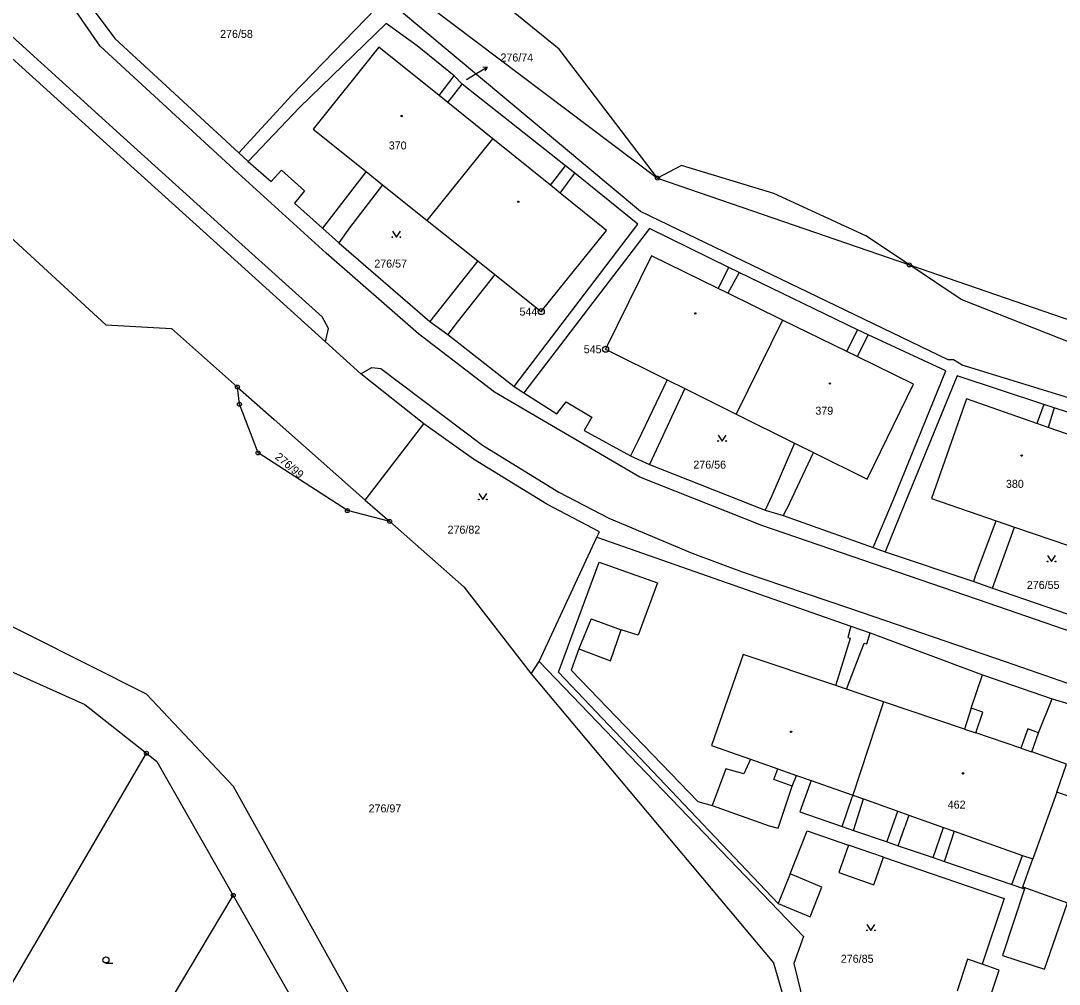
# Model space of a CAD drawing. Extents: x -745926 to -742978, y -968282 to -965689.
# Drawn here: x -744856.3 to -744726.5, y -967027 to -966906.6 of the extents above; entities that cross this region are included whole.
import ezdxf

# ---------------------------------------------------------------- set-up
doc = ezdxf.new("R2010")
doc.units = 0
for name, color, linetype in [('Hranice parcel', 7, 'Continuous'), ('Parcelní čísla', 7, 'Continuous'), ('Pop  PČ popisy', 7, 'Continuous'), ('Vnitřní kresba', 7, 'Continuous'), ('Značky bodu BP', 7, 'Continuous'), ('Značky budov', 7, 'Continuous'), ('Značky kultur', 7, 'Continuous')]:
    doc.layers.add(name, color=color, linetype=linetype)

msp = doc.modelspace()

# ---------------------------------------------------------------- linework, layer by layer
at = {"layer": 'Hranice parcel'}
for p, q in [((-744829.06, -966923.12), (-744827.88, -966924.19)), ((-744794.62, -966952.29), (-744793.43, -966953.08)), ((-744813.24, -966966.49), (-744805.93, -966956.99)), ((-744813.24, -966966.49), (-744810.19, -966969.17)), ((-744791.49, -966986.68), (-744784.3, -966971.12)), ((-744749.76, -966972.44), (-744748.26, -966972.98)), ((-744792.49, -966988.21), (-744791.49, -966986.68)), ((-744866.87, -967042.98), (-744840.6, -966998.13)), ((-744850.19, -967050.17), (-744829.75, -967015.89)), ((-744829.75, -967015.89), (-744805.47, -967058.42))]:
    msp.add_line(p, q, dxfattribs=at)
for points in [[(-744627.78, -966987.01), (-744649.71, -966979.39), (-744654.61, -966977.79), (-744692.27, -966963.9), (-744738.66, -966949.62), (-744739.71, -966948.97), (-744740.38, -966948.96), (-744778.84, -966930.46), (-744815.82, -966899.53), (-744818.58, -966883.89), (-744822.45, -966860.57), (-744822.45, -966858.85), (-744822.42, -966856.77), (-744822.4, -966854.94), (-744822.37, -966853.08), (-744822.37, -966851.59), (-744822.35, -966814.99), (-744823.48, -966815.03), (-744822.59, -966803.93), (-744824.77, -966768.68), (-744832.65, -966757.45)], [(-744812.79, -966854.17), (-744813.4, -966862.64), (-744813.73, -966867.2), (-744808, -966902.66), (-744776.73, -966926.26), (-744745.23, -966937.12), (-744720.11, -966945.77), (-744707.11, -966950.26), (-744691.81, -966955.53), (-744673.4, -966962.06), (-744650.22, -966970.28), (-744647.24, -966971.34)], [(-744805.93, -966956.99), (-744813.81, -966950.73), (-744818.23, -966946.73), (-744830.92, -966935.24), (-744845.58, -966922), (-744860.15, -966908.86), (-744870.54, -966900.46), (-744883.43, -966892.96), (-744896.32, -966886.96), (-744915.31, -966879.05), (-744921.62, -966878.86)], [(-744829.06, -966923.12), (-744822.41, -966915.9), (-744811.89, -966905.04), (-744817.34, -966900.06), (-744819.79, -966885.67), (-744822.12, -966886.29)], [(-744851.07, -966894.18), (-744849.82, -966901.7), (-744844.56, -966908.83), (-744829.06, -966923.12)], [(-744794.62, -966952.29), (-744779.16, -966932.02), (-744787.05, -966925.66), (-744788.22, -966924.73), (-744801.14, -966914.51), (-744802.14, -966913.51), (-744806.78, -966909.73), (-744810.65, -966906.94), (-744821.48, -966917.45), (-744827.88, -966924.19)], [(-744813.15, -966925.46), (-744811.1, -966927.1), (-744805.51, -966931.56), (-744799.19, -966936.61), (-744797.05, -966938.32), (-744791.25, -966942.95), (-744783.08, -966932.8), (-744788.9, -966928.13), (-744790.1, -966927.16), (-744797.32, -966921.35), (-744802.94, -966916.83), (-744804.02, -966915.96), (-744811.54, -966909.91), (-744819.77, -966920.17), (-744813.15, -966925.46)], [(-744870.98, -966921.46), (-744870.18, -966922.09), (-744845.67, -966944.6), (-744837.47, -966945.06), (-744829.23, -966952.37)], [(-744827.88, -966924.19), (-744825.01, -966926.7), (-744823.71, -966925.27), (-744820.86, -966927.86), (-744822.1, -966929.38), (-744818.6, -966932.53), (-744816.53, -966934.37), (-744805.18, -966944.17), (-744802.92, -966945.82), (-744794.62, -966952.29)], [(-744749.76, -966972.44), (-744747.21, -966966.42), (-744740.69, -966950.35), (-744750.39, -966945.85), (-744751.74, -966945.22), (-744766.5, -966938.08), (-744767.81, -966937.44), (-744777.71, -966932.57), (-744784.82, -966941.8), (-744793.43, -966953.08)], [(-744751.78, -966948.56), (-744753.06, -966947.94), (-744761.1, -966944), (-744767.94, -966940.65), (-744769.12, -966940.07), (-744777.47, -966935.98), (-744783.2, -966947.65), (-744775.53, -966951.46), (-744773.3, -966952.57), (-744766.87, -966955.76), (-744759.59, -966959.37), (-744757.21, -966960.55), (-744750.53, -966963.87), (-744744.73, -966952.02), (-744751.78, -966948.56)], [(-744801.42, -967053.13), (-744829.73, -967002.3), (-744840.61, -966990.76), (-744899.94, -966960.94), (-744893.56, -966949.44), (-744885.46, -966938.19)], [(-744707.55, -966984.87), (-744700.13, -966963.82), (-744710.14, -966960.53), (-744711.51, -966960.06), (-744727.15, -966954.96), (-744728.44, -966954.54), (-744739.28, -966950.98), (-744745.85, -966967), (-744748.26, -966972.98)], [(-744829.23, -966952.37), (-744824.63, -966956.44), (-744813.24, -966966.49)], [(-744810.19, -966969.17), (-744815.48, -966967.82), (-744826.65, -966960.6), (-744828.97, -966954.53), (-744829.23, -966952.37)], [(-744793.43, -966953.08), (-744789.32, -966955.71), (-744788.15, -966954.23), (-744784.94, -966956.12), (-744785.88, -966957.82), (-744780.09, -966960.97), (-744777.72, -966962.05), (-744763.27, -966967.75), (-744761.02, -966968.44), (-744749.76, -966972.44)], [(-744732.08, -966969.87), (-744725.21, -966972.23), (-744717.35, -966974.93), (-744715.13, -966975.69), (-744707.94, -966978.16), (-744703.71, -966965.87), (-744710.92, -966963.35), (-744712.38, -966962.84), (-744720.91, -966959.86), (-744727.9, -966957.42), (-744729.3, -966956.93), (-744738.11, -966953.85), (-744742.47, -966966.3), (-744734.37, -966969.08), (-744732.08, -966969.87)], [(-744784.3, -966971.12), (-744783.97, -966970.46), (-744790.56, -966967.02), (-744799.7, -966961.4), (-744805.93, -966956.99)], [(-744810.19, -966969.17), (-744800.91, -966977.33), (-744792.49, -966988.21)], [(-744784.3, -966971.12), (-744752.54, -966982.26), (-744750.13, -966983.09), (-744736.11, -966988.32), (-744727.4, -966991.33), (-744719.35, -966993.73), (-744716.91, -966994.58), (-744708.53, -966997.5), (-744707.88, -966999.67), (-744707.48, -967001.85), (-744707.64, -967006.3), (-744708.35, -967009.41), (-744707.68, -967009.55)], [(-744748.26, -966972.98), (-744737.18, -966976.65), (-744734.84, -966977.5), (-744720.2, -966982.53), (-744717.89, -966983.4), (-744710.13, -966986.07), (-744709.48, -966984.27), (-744707.55, -966984.87)], [(-744722.5, -967004.51), (-744726.82, -967002.98), (-744725.58, -966999.49), (-744729.94, -966997.94), (-744729.09, -966995.57), (-744730.42, -966995.09), (-744731.3, -966997.48), (-744736.93, -966995.58), (-744736.06, -966992.99), (-744737.5, -966992.48), (-744738.33, -966995.11), (-744748.47, -966991.7), (-744753.09, -966990.14), (-744754.45, -966989.68), (-744766, -966985.79), (-744769.95, -966997.15), (-744765.1, -966998.86), (-744765.93, -967000.69), (-744768.17, -967000.06), (-744769.87, -967004.65), (-744762.77, -967007.18), (-744761.65, -967007.49), (-744759.88, -967002.24), (-744759.36, -967000.89), (-744757.53, -967001.53), (-744758.93, -967005.47), (-744753.62, -967007.29), (-744752.21, -967007.77), (-744748.03, -967009.2), (-744746.62, -967009.68), (-744742.27, -967011.17), (-744740.85, -967011.66), (-744732.43, -967014.54), (-744730.86, -967015.09), (-744731.04, -967014.83), (-744725.48, -967016.81)], [(-744860.36, -966986.63), (-744860.03, -966986.8), (-744848.3, -966992.03), (-744840.6, -966998.13)], [(-744791.49, -966986.68), (-744758.49, -967021.01), (-744759.69, -967024.38), (-744751.69, -967057.23), (-744732.33, -967067.52)], [(-744792.49, -966988.21), (-744762.21, -967024.32), (-744758.14, -967038.46), (-744754.15, -967056.1), (-744750.35, -967061.52), (-744743.87, -967066.86)], [(-744840.6, -966998.13), (-744839.28, -966999.18), (-744829.75, -967015.89)]]:
    msp.add_lwpolyline(points, dxfattribs=at)
at = {"layer": 'Pop  PČ popisy'}
for p, q in [((-744800.58, -966913.96), (-744799.29, -966913.17)), ((-744799.29, -966913.17), (-744798, -966912.4)), ((-744798, -966912.4), (-744798.56, -966912.44)), ((-744798, -966912.4), (-744798.3, -966912.87))]:
    msp.add_line(p, q, dxfattribs=at)
at = {"layer": 'Vnitřní kresba'}
for p, q in [((-744789.03, -966910.15), (-744800.9, -966900.5)), ((-744846.39, -966909.77), (-744851.69, -966902.1)), ((-744844.34, -966920.42), (-744858.77, -966907.33)), ((-744829.13, -966925.67), (-744846.39, -966909.77)), ((-744776.73, -966926.26), (-744789.03, -966910.15)), ((-744804.02, -966915.96), (-744802.14, -966913.51)), ((-744802.94, -966916.83), (-744801.14, -966914.51)), ((-744829.52, -966933.83), (-744844.34, -966920.42)), ((-744805.51, -966931.56), (-744797.32, -966921.35)), ((-744790.1, -966927.16), (-744788.22, -966924.73)), ((-744773.72, -966924.7), (-744776.73, -966926.26)), ((-744762.16, -966928.21), (-744773.72, -966924.7)), ((-744818.12, -966935.65), (-744829.13, -966925.67)), ((-744813.15, -966925.46), (-744818.6, -966932.53)), ((-744788.9, -966928.13), (-744787.05, -966925.66)), ((-744811.1, -966927.1), (-744815.22, -966932.47)), ((-744750.67, -966933.5), (-744762.16, -966928.21)), ((-744815.22, -966932.47), (-744816.53, -966934.37)), ((-744818.62, -966943.6), (-744829.52, -966933.83)), ((-744745.23, -966937.12), (-744750.67, -966933.5)), ((-744806.61, -966945.72), (-744818.12, -966935.65)), ((-744799.19, -966936.61), (-744805.18, -966944.17)), ((-744769.12, -966940.07), (-744767.81, -966937.44)), ((-744738.76, -966941.42), (-744745.23, -966937.12)), ((-744797.05, -966938.32), (-744801.77, -966944.26)), ((-744766.5, -966938.08), (-744767.94, -966940.65)), ((-744722.67, -966947.78), (-744738.76, -966941.42)), ((-744817.83, -966945.06), (-744818.62, -966943.6)), ((-744801.77, -966944.26), (-744802.92, -966945.82)), ((-744761.1, -966944), (-744766.87, -966955.76)), ((-744818.23, -966946.73), (-744817.83, -966945.06)), ((-744797.09, -966953.02), (-744806.61, -966945.72)), ((-744753.06, -966947.94), (-744751.74, -966945.22)), ((-744750.39, -966945.85), (-744751.78, -966948.56)), ((-744813.81, -966950.73), (-744812.44, -966949.95)), ((-744812.44, -966949.95), (-744811.28, -966950.04)), ((-744811.28, -966950.04), (-744798.59, -966959.63)), ((-744775.53, -966951.46), (-744779.16, -966959.12)), ((-744778.92, -966963.64), (-744797.09, -966953.02)), ((-744773.3, -966952.57), (-744777.72, -966962.05)), ((-744728.44, -966954.54), (-744729.3, -966956.93)), ((-744727.15, -966954.96), (-744727.9, -966957.42)), ((-744798.59, -966959.63), (-744789.04, -966965.52)), ((-744779.16, -966959.12), (-744780.09, -966960.97)), ((-744759.59, -966959.37), (-744762.45, -966965.96)), ((-744760.21, -966966.93), (-744757.21, -966960.55)), ((-744763.67, -966969.67), (-744778.92, -966963.64)), ((-744789.04, -966965.52), (-744782.79, -966968.74)), ((-744762.45, -966965.96), (-744763.27, -966967.75)), ((-744760.21, -966966.93), (-744761.02, -966968.44)), ((-744782.79, -966968.74), (-744772.38, -966973.11)), ((-744736.96, -966975.96), (-744734.37, -966969.08)), ((-744735.4, -966979.39), (-744763.67, -966969.67)), ((-744734.84, -966977.5), (-744732.08, -966969.87)), ((-744789.1, -966987.98), (-744784, -966974.24)), ((-744784, -966974.24), (-744776.71, -966976.83)), ((-744772.38, -966973.11), (-744766.12, -966975.45)), ((-744766.12, -966975.45), (-744752.85, -966979.96)), ((-744776.71, -966976.83), (-744779.13, -966983.36)), ((-744737.18, -966976.65), (-744736.96, -966975.96)), ((-744718.5, -966985.23), (-744735.4, -966979.39)), ((-744752.85, -966979.96), (-744733.16, -966986.72)), ((-744785.03, -966981.33), (-744786.55, -966985.07)), ((-744785.03, -966981.33), (-744781.28, -966982.71)), ((-744782.61, -966986.6), (-744781.28, -966982.71)), ((-744779.13, -966983.36), (-744781.28, -966982.71)), ((-744752.54, -966982.26), (-744752.95, -966983.65)), ((-744750.54, -966984.48), (-744750.13, -966983.09)), ((-744754.45, -966989.68), (-744752.6, -966983.77)), ((-744753.09, -966990.14), (-744750.9, -966984.36)), ((-744752.95, -966983.65), (-744752.6, -966983.77)), ((-744750.9, -966984.36), (-744750.54, -966984.48)), ((-744786.55, -966985.07), (-744787.53, -966987.74)), ((-744786.55, -966985.07), (-744782.61, -966986.6)), ((-744733.16, -966986.72), (-744712.88, -966993.72)), ((-744789.1, -966987.98), (-744761.65, -967016.91)), ((-744787.53, -966987.74), (-744771.67, -967004.14)), ((-744737.5, -966992.48), (-744736.11, -966988.32)), ((-744748.47, -966991.7), (-744752.31, -967003.37)), ((-744729.09, -966995.57), (-744727.4, -966991.33)), ((-744738.33, -966995.11), (-744736.93, -966995.58)), ((-744731.3, -966997.48), (-744729.94, -966997.94)), ((-744765.1, -966998.86), (-744761.68, -967000.07)), ((-744762.16, -967001.41), (-744761.68, -967000.07)), ((-744761.68, -967000.07), (-744759.36, -967000.89)), ((-744759.88, -967002.24), (-744762.16, -967001.41)), ((-744757.53, -967001.53), (-744752.31, -967003.37)), ((-744753.62, -967007.29), (-744752.39, -967003.62)), ((-744752.31, -967003.37), (-744752.39, -967003.62)), ((-744752.31, -967003.37), (-744750.99, -967003.84)), ((-744751.46, -967005.41), (-744750.99, -967003.84)), ((-744750.99, -967003.84), (-744746.67, -967005.37)), ((-744726.82, -967002.98), (-744729.8, -967011.34)), ((-744771.67, -967004.14), (-744769.87, -967004.65)), ((-744752.21, -967007.77), (-744751.46, -967005.41)), ((-744748, -967009.12), (-744746.67, -967005.37)), ((-744746.67, -967005.37), (-744745.29, -967005.86)), ((-744745.29, -967005.86), (-744745.79, -967007.31)), ((-744745.29, -967005.86), (-744740.97, -967007.39)), ((-744760.14, -967013.2), (-744758, -967007.83)), ((-744758, -967007.83), (-744752.85, -967009.62)), ((-744746.62, -967009.68), (-744745.79, -967007.31)), ((-744742.27, -967011.17), (-744740.97, -967007.39)), ((-744740.97, -967007.39), (-744739.65, -967007.86)), ((-744739.65, -967007.86), (-744740.11, -967009.29)), ((-744739.65, -967007.86), (-744731.08, -967010.89)), ((-744748.03, -967009.2), (-744748, -967009.12)), ((-744740.11, -967009.29), (-744740.83, -967011.59)), ((-744752.85, -967009.62), (-744754.07, -967013.04)), ((-744748.47, -967011.12), (-744752.85, -967009.62)), ((-744749.68, -967014.56), (-744748.47, -967011.12)), ((-744748.47, -967011.12), (-744733.37, -967016.27)), ((-744740.85, -967011.66), (-744740.83, -967011.59)), ((-744732.43, -967014.54), (-744731.08, -967010.89)), ((-744731.08, -967010.89), (-744729.8, -967011.34)), ((-744731.04, -967014.83), (-744729.8, -967011.34)), ((-744760.14, -967013.2), (-744761.65, -967016.91)), ((-744756.2, -967014.88), (-744760.14, -967013.2)), ((-744754.07, -967013.04), (-744749.68, -967014.56)), ((-744757.63, -967018.59), (-744756.2, -967014.88)), ((-744730.86, -967015.09), (-744733.59, -967023.41)), ((-744761.65, -967016.91), (-744757.63, -967018.59)), ((-744733.37, -967016.27), (-744736.13, -967024.5)), ((-744728.35, -967025.12), (-744725.48, -967016.81)), ((-744733.59, -967023.41), (-744728.35, -967025.12)), ((-744737.99, -967023.88), (-744739.26, -967027.86)), ((-744736.13, -967024.5), (-744737.99, -967023.88)), ((-744734.03, -967025.23), (-744736.13, -967024.5)), ((-744735.33, -967029.22), (-744734.03, -967025.23))]:
    msp.add_line(p, q, dxfattribs=at)
at = {"layer": 'Značky bodu BP'}
for centre, radius in [((-744776.73, -966926.26), 0.25), ((-744776.73, -966926.26), 0.0152), ((-744745.23, -966937.12), 0.25), ((-744745.23, -966937.12), 0.0152), ((-744791.25, -966942.95), 0.375), ((-744791.25, -966942.95), 0.015), ((-744783.2, -966947.65), 0.375), ((-744783.2, -966947.65), 0.015), ((-744829.23, -966952.37), 0.25), ((-744829.23, -966952.37), 0.0152), ((-744828.97, -966954.53), 0.25), ((-744828.97, -966954.53), 0.0152), ((-744826.65, -966960.6), 0.25), ((-744826.65, -966960.6), 0.0152), ((-744815.48, -966967.82), 0.25), ((-744815.48, -966967.82), 0.0152), ((-744810.19, -966969.17), 0.25), ((-744810.19, -966969.17), 0.0152), ((-744840.6, -966998.13), 0.25), ((-744840.6, -966998.13), 0.0152), ((-744829.75, -967015.89), 0.25), ((-744829.75, -967015.89), 0.0152)]:
    msp.add_circle(centre, radius, dxfattribs=at)
at = {"layer": 'Značky budov'}
for centre in [(-744808.68, -966918.51), (-744794.13, -966929.22), (-744772, -966943.18), (-744755.18, -966951.93), (-744731.2, -966960.93), (-744760.02, -966995.45), (-744738.54, -967000.64)]:
    msp.add_circle(centre, 0.0875, dxfattribs=at)
at = {"layer": 'Značky kultur'}
msp.add_line((-744845.66, -967024.34), (-744844.78, -967024.34), dxfattribs=at)
for points in [[(-744809.86, -966932.89), (-744809.36, -966933.64), (-744808.86, -966932.89)], [(-744769.13, -966958.37), (-744768.63, -966959.12), (-744768.13, -966958.37)], [(-744799.05, -966965.68), (-744798.55, -966966.43), (-744798.05, -966965.68)], [(-744727.96, -966973.43), (-744727.46, -966974.18), (-744726.96, -966973.43)], [(-744750.54, -967019.51), (-744750.04, -967020.26), (-744749.54, -967019.51)]]:
    msp.add_lwpolyline(points, dxfattribs=at)
for centre, radius in [((-744809.86, -966933.64), 0.05), ((-744808.86, -966933.64), 0.05), ((-744769.13, -966959.12), 0.05), ((-744768.13, -966959.12), 0.05), ((-744799.05, -966966.43), 0.05), ((-744798.05, -966966.43), 0.05), ((-744727.96, -966974.18), 0.05), ((-744726.96, -966974.18), 0.05), ((-744750.54, -967020.26), 0.05), ((-744749.54, -967020.26), 0.05), ((-744845.66, -967023.96), 0.375)]:
    msp.add_circle(centre, radius, dxfattribs=at)

# ---------------------------------------------------------------- texts
at = {"layer": 'Parcelní čísla'}
for s, p in [('276/58', (-744831.39, -966908.75)), ('276/74', (-744796.35, -966911.7)), ('370', (-744810.31, -966922.69)), ('276/57', (-744812.12, -966937.45)), ('379', (-744756.99, -966955.83)), ('276/56', (-744772.24, -966962.57)), ('380', (-744733.17, -966964.97)), ('276/82', (-744802.96, -966970.69)), ('276/55', (-744730.56, -966977.6)), ('462', (-744740.45, -967005.05)), ('276/97', (-744812.83, -967005.52)), ('276/85', (-744753.81, -967024.31))]:
    msp.add_text(s, height=1, dxfattribs=at).set_placement(p)
msp.add_text('276/99', height=1, rotation=320, dxfattribs=at).set_placement((-744824.6, -966961.24))
at = {"layer": 'Značky bodu BP'}
for s, p in [('544', (-744793.97, -966943.45)), ('545', (-744785.94, -966948.15))]:
    msp.add_text(s, height=1, dxfattribs=at).set_placement(p)

doc.saveas('drawing.dxf')
